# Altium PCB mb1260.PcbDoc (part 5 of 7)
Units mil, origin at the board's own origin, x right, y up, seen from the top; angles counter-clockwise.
Board outline 3189.01 x 3818.89 mil, 6 copper layers (TOP, L2_GND, L3_VCC, L4_SIG, L5_GND, BOTTOM), stack 62.2 mil thick; 308 components, 287 nets, 1220 pads, 851 vias.
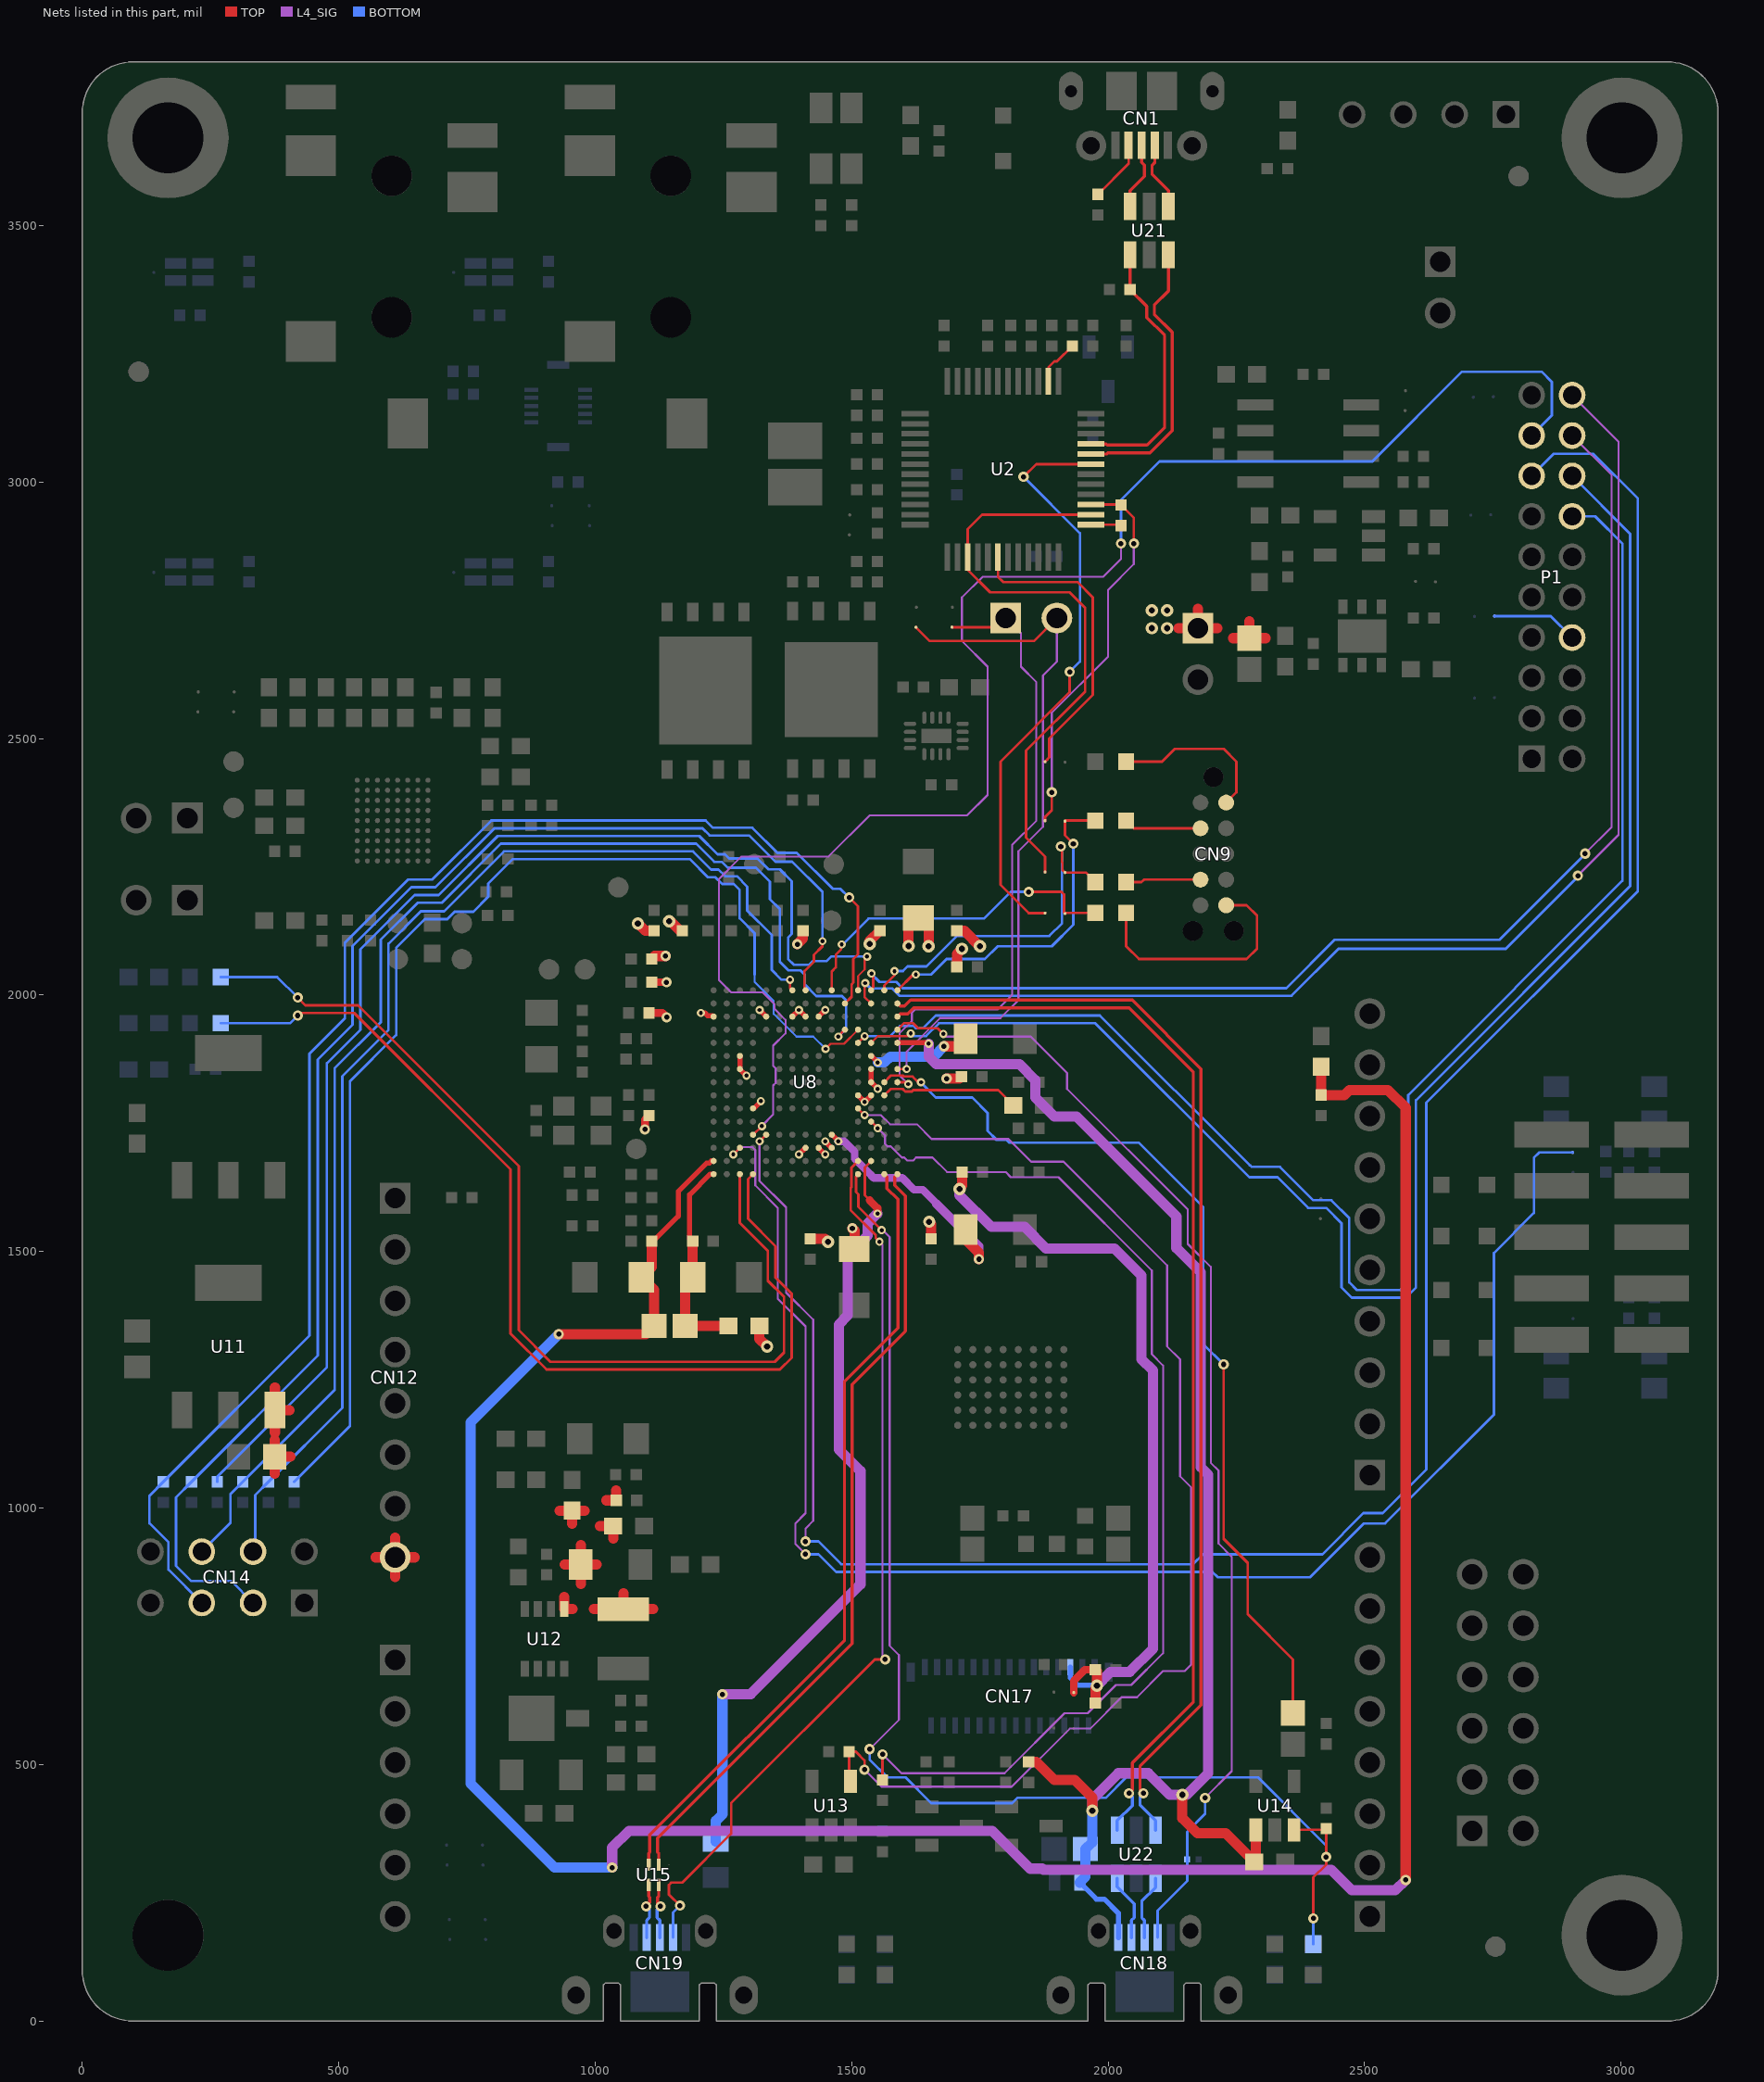
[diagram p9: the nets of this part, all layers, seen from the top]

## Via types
v1: diameter 24, hole 12, TOP to BOTTOM, tented both sides, 389 vias
v2: diameter 20, hole 10, TOP to BOTTOM, tented both sides, 231 vias
v3: diameter 16, hole 8, TOP to BOTTOM, tented both sides, 196 vias
v4: diameter 12, hole 6, TOP to BOTTOM, tented both sides, 35 vias

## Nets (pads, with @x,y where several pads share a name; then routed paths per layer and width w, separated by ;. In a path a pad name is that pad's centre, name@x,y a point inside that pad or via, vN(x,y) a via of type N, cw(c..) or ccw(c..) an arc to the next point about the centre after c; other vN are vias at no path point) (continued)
STMOD+_SPI2_MISOS: P1.9 U8.M4 | length 3145.4
  TOP w5: U8.M4@1307.64,1727.64 1308.14,1727.64 1325,1744.5 v3(1325.1,1744.5)
  L4_SIG w4: v3(1325.1,1744.5) 1325.1,1745.1 1347,1767 1347,1823.71 1352,1828.71 1352,1856.88 1347,1861.88 1347,1901.32 1371,1925.32 1371,1951.69 1349.68,1973.01 1349.68,1981.99 1326.68,2005 1265,2005 1241,2029 1241,2226 1285,2270 1455,2270 1535,2350 1725,2350 1765,2390 1765,2640 1715,2690 1715,2775 1755,2815 1990,2815 2025,2850 v2(2025,2880)
  BOTTOM w5: v2(2025,2880) 2025,2965 2100,3040 2515,3040 2690,3215 2845,3215 2865,3195 2865,3129.92 P1.9@2825.63,3090.55
STMOD+_SPI2_MOSIS: P1.8 U8.M5 | length 4476.8
  TOP w5: v3(1320.37,1714.91) 1320.5,1714.91 U8.M5@1333.23,1727.64
  L4_SIG w4: v3(1320.37,1714.91) 1320.37,1637.61 1372,1585.98 1372,1420 1425,1367 1425,975 1410,960 v2(1410,935)
  BOTTOM w5: v2(1410,935) 1435,935 1479.5,890.5 2165.5,890.5 2185,910 2417.56,910 2497.56,990 2535,990 2620,1075 2620,1790 3032.5,2202.5 3032.5,2967.5 2945,3055 2868.82,3055 P1.8@2825.63,3011.81
STMOD+_TIM2_CH1: P1.19 U8.A13 | length 2418.8
  TOP w5: U8.A13@1537.95,2009.13 1537.95,2010.08 1542.04,2014.17 1542.04,2037.96 1538.09,2041.91 v3(1538.52,2041.91)
  L4_SIG w4: P1.19@2904.37,3090.55 2981.57,3013.35 2981.57,2327.53 v2(2929.65,2275.61)
  BOTTOM w5: v3(1538.52,2041.91) 1537.63,2041.91 1554.06,2025.48 1586.81,2025.48 1598.79,2013.5 2347.51,2013.5 2441.68,2107.67 2762.67,2107.67 2929.65,2274.65 v2(2929.65,2275.61)
STMOD+_TIM3_CH3: P1.14 SB29.1 | length 168.7
  BOTTOM w5: SB29.1@2753.01,2738.67 2862.55,2738.67 P1.14@2904.37,2696.85
STMOD+_UART4_RXD: P1.18 U8.E13 | length 3186.7
  TOP w4: U8.E13@1537.95,1906.77 1550.86,1919.68 1609.68,1919.68 v3(1615,1925)
  BOTTOM w5: v3(1615,1925) 1620,1920 1645,1920 1670,1945 1975,1945 2275,1645 2330,1645 2390,1585 2425,1585 2455,1555 2455,1430 2475,1410 2580,1410 2600,1430 2600,1795 3017.5,2212.5 3017.5,2898.68 P1.18@2904.37,3011.81
STMOD+_UART4_RXD_S: P1.20 U8.B13 | length 2550.4
  TOP w5: v3(1526.47,2023.28) 1525,2021.81 1525,1996.49 U8.B13@1537.95,1983.54
  L4_SIG w4: P1.20@2904.37,3169.29 2995.03,3078.63 2995.03,2312.13 v2(2915.53,2232.63)
  BOTTOM w5: v3(1526.47,2023.28) 1536.92,2012.83 1578.63,2012.83 1592.96,1998.5 2357.5,1998.5 2449,2090 2775,2090 2915.53,2230.53 v2(2915.53,2232.63)
STMOD+_UART4_TXD: P1.17 U8.E12 | length 3132.5
  TOP w5: U8.E12@1512.36,1906.77 v3(1525.22,1919.63)
  BOTTOM w5: v3(1525.22,1919.63) 1574.63,1919.63 1594.5,1939.5 1621.01,1939.5 1625.51,1935 1638.78,1935 1663.78,1960 1983.78,1960 2275.78,1668 2277,1668 2280,1665 2335,1665 2400,1600 2435,1600 2470,1565 2470,1440 2485,1425 2570,1425 2585,1440 2585,1805 3002.5,2222.5 3002.5,2879.94 2949.37,2933.07 P1.17@2904.37,2933.07
SYS_B_USER: SB33.1 U8.N3 | length 3018.9
  TOP w5: v3(1269.19,1689.19) U8.N3@1282.05,1702.05
  L4_SIG w4: v3(1269.19,1689.19) 1283.32,1703.32 1306.5,1703.32 1312,1697.82 1312,1629 1356,1585 1356,1408 1410,1354 1410,990 1390,970 1390,930 v2(1410,910)
  BOTTOM w5: v2(1410,910) 1435,910 1469.5,875.5 2203.04,875.5 2213.54,865 2393.78,865 2498.78,970 2540,970 2752,1182 2752,1497 2830,1575 2830,1683.01 2840,1693.01 SB33.1@2905.33,1693.01
SYS_LD_USER1: R47.1 U8.R3 | length 1987
  TOP w5: v2(420,1995) 435,1980 537.63,1980 851,1666.63 851,1346.63 912.63,1285 1350,1285 1368,1303 1368,1411.56 1336.5,1443.06 1336.5,1501.5 1282.05,1555.95 U8.R3@1282.05,1650.87
  BOTTOM w5: R47.1@270,2035 380,2035 v2(420,1995)
SYS_LD_USER2: R48.1 U8.R4 | length 2003.2
  TOP w5: v2(420,1960) 425,1965 530,1965 835,1660 835,1340 905,1270 1360,1270 1383,1293 1383,1417.78 1351.5,1449.28 1351.5,1510.5 1298,1564 1298,1641.23 U8.R4@1307.64,1650.87
  BOTTOM w5: R48.1@270,1945 405,1945 v2(420,1960)
SYS_STLINK_JTCK: R38.2 SB12.2 U8.A14 | length 682.4
  TOP w5: U8.A14@1563.54,2009.13 1563.54,2018.54 1583.39,2038.39 v3(1583.39,2046.61) ; v2(1907.62,2289.45) 1910,2287.07 1910,2258.91 1910.69,2258.22 1910.69,2243.95 SB12.2@1915.83,2238.81 1956.19,2238.81 R38.2@1975,2220
  BOTTOM w5: v3(1583.39,2046.61) 1600,2046.61 1608.89,2055.5 1645.5,2055.5 1705,2115 1885,2115 1910,2140 1910,2287.07 v2(1907.62,2289.45)
SYS_STLINK_JTDO-SWO: R40.2 SB13.2 U8.A10 | length 673
  TOP w5: U8.A10@1461.18,2009.13 1461.18,2046.18 1469,2054 1469,2078.52 1479,2088.52 1479,2097.06 v3(1480.47,2098.53) ; v2(1845,2201) 1909,2201 1914,2196 1914,2160.64 SB13.2@1915.83,2158.81 1917.02,2160 R40.2@1975,2160
  BOTTOM w5: v3(1480.47,2098.53) 1482.53,2098.53 1533,2149 1758,2149 1810,2201 v2(1845,2201)
SYS_STLINK_JTMS: R32.2 SB11.2 U8.A15 | length 664
  TOP w5: U8.A15@1589.13,2009.13 1620,2040 v3(1625,2040) ; v2(1932,2295) 1915.83,2311.17 SB11.2@1915.83,2338.81 1917.02,2340 R32.2@1975,2340
  BOTTOM w5: v3(1625,2040) 1655,2040 1684.96,2069.96 1759.46,2069.96 1784.5,2095 1890,2095 1932,2137 v2(1932,2295)
T_JTCK: SB12.1 U2.15 U2.26 | length 1168.9
  TOP w5: SB12.1@1876.99,2239.67 1876.99,2270 1840,2306.99 1840,2476.22 1955,2591.22 1955,2755 1925,2785 1770,2785 1726.1,2828.9 U2.15@1726.1,2853.74 1726.1,2908.1 1754.42,2936.42 U2.26@1966.26,2936.42
T_JTMS: R23.1 SB11.1 U2.27 | length 756.5
  TOP w5: SB11.1@1876.99,2339.67 1876.99,2346.99 1890,2360 v2(1890,2395) ; U2.27@1966.26,2956.1 2023.9,2956.1 R23.1@2025,2955 2050,2930 v2(2050,2880)
  L4_SIG w4: v2(1890,2395) 1890,2550 2000,2660 2000,2790 2050,2840 v2(2050,2880)
T_NRST: SB10.1 U2.18 | length 599
  TOP w5: U2.18@1785.16,2853.74 1785.16,2815 1795.16,2805 1940,2805 1970,2775 1970,2585 1885,2500 1885,2463.07 1882.1,2460.17 1882.1,2459.78 SB10.1@1876.99,2454.67
T_SWDIO_IN: R23.2 U2.25 | length 59.5
  TOP w5: U2.25@1966.26,2916.73 2023.27,2916.73 R23.2@2025,2915
T_SWO: SB13.1 U2.31 | length 1156.4
  TOP w5: v2(1835,3010) 1859.84,3034.84 U2.31@1966.26,3034.84 ; SB13.1@1876.99,2159.67 1845,2159.67 1790,2214.67 1790,2455 1925,2590 v2(1925,2630)
  BOTTOM w5: v2(1835,3010) 1945,2900 1945,2650 v2(1925,2630)
TAG_NRST: CN9.10 R28.1 | length 323.8
  TOP w5: R28.1@2035,2455 2105,2455 2129.79,2479.79 2225.21,2479.79 2250,2455 2250,2395 CN9.10@2230,2375
TAG_SWCLK: CN9.4 R38.1 | length 147.1
  TOP w5: R38.1@2035,2220 2065,2220 2070,2225 CN9.4@2180,2225
TAG_SWDIO: CN9.2 R32.1 | length 151.2
  TOP w5: R32.1@2035,2340 2050,2325 CN9.2@2180,2325
TAG_SWO: CN9.6 R40.1 | length 471.9
  TOP w5: R40.1@2035,2160 2035,2095 2060,2070 2270,2070 2290,2090 2290,2155 2270,2175 CN9.6@2230,2175
USB_OTGFS_CN_N: CN18.2 U22.6 | length 130.8
  BOTTOM w6.1: U22.6@2017.6,277.76 2017.6,261.4 2050.57,228.43 2050.57,201.67 2045.28,196.38 CN18.2@2045.28,162.8
USB_OTGFS_CN_P: CN18.3 U22.4 | length 128.3
  BOTTOM w6.1: CN18.3@2070.87,162.8 2070.87,196.37 2065.57,201.67 2065.57,233.57 2092.4,260.4 U22.4@2092.4,277.76
USB_OTGFS_ID: CN18.4 U8.D15 U23.1 | length 2254.3
  TOP w5: U8.D15@1589.13,1932.36 1601.77,1945 1620,1945 1630,1935 1667.79,1935 v3(1678.63,1924.16)
  L4_SIG w4: v3(1678.63,1924.16) 1683.79,1919 1849,1919 1920,1848 1920,1817 2155,1582 2155,1515 2200,1470 2200,1088.29 2215,1073.29 2215,931 2241,905 2241,487 v2(2189,435)
  BOTTOM w5: CN18.4@2096.46,162.8 2096.46,215.44 2153.98,272.96 U23.1@2153.98,315 2153.98,368.98 2189,404 v2(2189,435)
USB_OTGFS_N: U8.C15 U22.1 | length 2180.2
  TOP w6.1: U8.C15@1589.13,1957.95 1594.42,1963.24 1609.46,1963.24 1621.22,1975 2040.78,1975 2166,1849.78 2166,622.22 2047.14,503.36 2047.14,450.36 v2(2040.64,443.86)
  BOTTOM w6.1: U22.1@2017.6,372.24 2017.6,390.6 2047.14,420.14 2047.14,437.36 v2(2040.64,443.86)
USB_OTGFS_OVCR: LD10.2 R79.1 U8.R12 U14.3 | length 2524.1
  TOP w5: U8.R12@1512.36,1650.87 1508.27,1646.78 1508.27,1615.95 1513,1611.22 1513,1587.29 v3(1558.47,1541.82) ; U14.3@2362.4,372.76 2422.76,372.76 R79.1@2425,375 v2(2425,320) 2425,305 2400,280 v2(2400,200)
  L4_SIG w4: v2(1535,530) 1592.11,587.11 1592.11,713.54 1574,731.65 1574,1528.44 1560.62,1541.82 v3(1558.47,1541.82)
  BOTTOM w5: v2(1535,530) 1535,510 1570,475 1605,475 1655,425 1813,425 1823,435 1995,435 2035,475 2292,475 2425,342 v2(2425,320) ; LD10.2@2400,150 v2(2400,200)
USB_OTGFS_P: U8.B15 U22.3 | length 2205.4
  TOP w6.1: U8.B15@1589.13,1983.54 1594.43,1978.24 1603.24,1978.24 1615,1990 2047,1990 2181,1856 2181,616 2062.14,497.14 2062.14,450.36 v2(2068.64,443.86)
  BOTTOM w6.1: v2(2068.64,443.86) 2062.14,437.36 2062.14,420.86 2092.4,390.6 U22.3@2092.4,372.24
USB_OTGFS_PPWR_EN: R72.1 U8.H14 | length 1812.9
  TOP w5: U8.H14@1563.54,1830 1576.54,1843 1599.21,1843 1601.12,1841.09 1618.91,1841.09 1630,1830 v3(1635,1830) ; v2(2225,1280) 2225,940 2272,893 2272,793 2360,705 R72.1@2360,600.51
  BOTTOM w5: v3(1635,1830) 1640,1825 1640,1824.02 1664.02,1800 1735,1800 1765,1770 1765,1735 1782.49,1717.5 1802.25,1717.5 1807.75,1712 2060,1712 2185,1587 2185,1320 v2(2225,1280)
USB_OTGFS_VBUS: C77.1 CN18.1 R77.2 R99.1 U8.E15 U14.1 U24.1 | length 2894.4
  TOP w10: U8.E15@1589.13,1906.77 1648.23,1906.77 v3(1650,1905)
  TOP w20: R77.2@1845,505 1860,505 1895,470 1935,470 1969,436 v1(1969,410) ; v1(2144.5,441) 2144.5,395.5 2174,366 2229,366 C77.1@2285,310 2287.6,312.6 U14.1@2287.6,372.76
  L4_SIG w20: v3(1650,1905) 1650,1880 1665,1865 1827,1865 1858,1834 1858,1800.41 1895.41,1763 1938,1763 2132.99,1568.01 2132.99,1507.01 2180,1460 2180,1080 2195,1065 2195,483 2153,441 v1(2144.5,441) 2120,441 2078,483 2020,483 1969,432 v1(1969,410)
  BOTTOM w10: U24.1@1944.61,270 1977.11,237.5 1992.5,237.5 2019.69,210.31 CN18.1@2019.69,162.8
  BOTTOM w20: U24.1@1944.61,270 1955.51,280.9 R99.1@1955.51,335 1969,348.49 v1(1969,410)
USB_OTGHS_CN_N: CN19.2 U15.2 | length 111.4
  TOP w6.1: v2(1099.18,223.76) 1106.5,231.08 1106.5,240.94 1104.16,243.28 U15.2@1104.16,265.31
  BOTTOM w6.1: v2(1099.18,223.76) 1105.68,217.26 1105.68,201.67 1100.39,196.38 CN19.2@1100.39,162.8
USB_OTGHS_CN_P: CN19.3 U15.3 | length 110.7
  TOP w6.1: U15.3@1123.84,265.31 1123.84,243.28 1121.5,240.94 1121.5,229.44 v2(1127.18,223.76)
  BOTTOM w6.1: CN19.3@1125.98,162.8 1125.98,196.37 1120.68,201.67 1120.68,217.26 v2(1127.18,223.76)
USB_OTGHS_ID: CN19.4 U8.P12 U15.4 | length 1760.9
  TOP w5: v2(1165,225) 1143.53,246.47 U15.4@1143.53,265.31 1148.22,270 1170,270 1265,365 1265,425 1545,705 v2(1565,705) ; U8.P12@1512.36,1676.46 1499.27,1663.37 1499.27,1625 1498,1623.73 1498,1580.4 1546.79,1531.61 1546.79,1526.21 v3(1554,1519)
  L4_SIG w4: v3(1554,1519) 1560,1513 1560,710 v2(1565,705)
  BOTTOM w5: CN19.4@1151.57,162.8 1151.57,211.57 v2(1165,225)
USB_OTGHS_N: U8.R14 U15.7 | length 1558.4
  TOP w6.1: U15.7@1104.16,304.69 1104.16,326.72 1106.5,329.06 1106.5,362.72 1486,742.22 1486,1247.22 1590,1351.22 1590,1601.78 1568.83,1622.95 1568.83,1645.58 U8.R14@1563.54,1650.87
USB_OTGHS_OVCR: R78.2 U8.L13 | length 2145.9
  TOP w5: U8.L13@1537.95,1753.23 v3(1550.81,1740.37) ; R78.2@1560,470 v2(1560,520)
  L4_SIG w4: v3(1550.81,1740.37) 1565,1726.18 1565,1710 1570,1705 1576.33,1705 1598.07,1683.26 1602.44,1683.26 1608.2,1677.5 1619.8,1677.5 1625.56,1683.26 1657.59,1683.26 1685.85,1655 1800,1655 1810,1645 1903.02,1645 2085,1463.02 2085,1300 2107,1278 2107,733.58 ; v2(1560,520) 1597,483 1798,483 1915,600 1960,600 2015,655 2045,655 2107.01,717.01 2107.01,733.57
USB_OTGHS_P: U8.R15 U15.6 | length 1558.4
  TOP w6.1: U15.6@1123.84,304.69 1123.84,326.72 1121.5,329.06 1121.5,356.5 1501,736 1501,1241 1605,1345 1605,1608 1583.83,1629.17 1583.83,1645.57 U8.R15@1589.13,1650.87
USB_OTGHS_PPWR_EN: R16.2 U8.K12 U13.4 | length 2389.8
  TOP w5: U13.4@1497.4,467.24 1495,469.64 R16.2@1495,525 1508,525 1525,508 v2(1525,490) ; U8.K12@1512.36,1778.82 v3(1525.22,1765.96)
  L4_SIG w4: v2(1525,490) 1558,457 1812,457 1925,570 1965,570 2026,631 2056,631 2107,682 2149,682 2162,695 2162,1040 2140,1062 2140,1290 2115,1315 2115,1473 1913,1675 1850,1675 1805.5,1719.5 1655.5,1719.5 1627,1748 1575,1748 1557.04,1765.96 v3(1525.22,1765.96)
USB_OTGHS_VBUS: R98.1 U8.P13 | length 1539.6
  TOP w5: 1535,1600 1525.45,1609.55 1525.45,1663.96 U8.P13@1537.95,1676.46
  TOP w15: 1535,1600 1550.32,1584.68 v3(1550.32,1574)
  L4_SIG w20: v2(1248,637) 1303,637 1517,851 1517,1072 1475,1114 1475,1358 1492.49,1375.49 1492.49,1492.49 1531,1531 1531,1554.68 v3(1550.32,1574)
  BOTTOM w20: R98.1@1235,350 1235,390 1248,403 v2(1248,637)
USB_RENUMN: R7.2 U2.38 | length 90.9
  TOP w5: U2.38@1883.58,3196.26 1883.58,3223.58 1895,3235 1900,3235 R7.2@1930,3265
USB_STLK_CN_N: CN1.2 U21.1 | length 134.6
  TOP w6.1: CN1.2@2090.94,3656.49 2090.94,3622.92 2085.64,3617.62 2085.64,3599.36 2117.4,3567.6 U21.1@2117.4,3537.24
USB_STLK_CN_P: CN1.3 U21.3 | length 133.1
  TOP w6.1: U21.3@2042.6,3537.24 2042.6,3567.6 2070.64,3595.64 2070.64,3617.62 2065.35,3622.91 CN1.3@2065.35,3656.49
USB_STLK_ID: CN1.4 R9.2 | length 120.7
  TOP w5: R9.2@1980,3560.59 2039.76,3620.35 CN1.4@2039.76,3656.49
USB_STLK_N: U2.32 U21.6 | length 546.2
  TOP w6.1: U2.32@1966.26,3054.53 1996.66,3054.53 1999,3056.87 2081.87,3056.87 2125,3100 2125,3292 2090,3327 2090,3345 2117.4,3372.4 U21.6@2117.4,3442.76
USB_STLK_P: R10.2 U2.33 U21.4 | length 523.4
  TOP w6.1: U2.33@1966.26,3074.21 1995.66,3074.21 1998,3071.87 2075.65,3071.87 2110,3106.22 2110,3285.78 2075,3320.78 2075,3342.6 R10.2@2042.6,3375 U21.4@2042.6,3442.76
V12_OTGPHY: C54.1 U8.J14 | length 272
  TOP w5: U8.J14@1563.54,1804.41 1576.04,1816.91 1599.25,1816.91 1604.25,1811.91 1617.42,1811.91 1620,1814.49 1785.51,1814.49 C54.1@1815,1785
VCAP1: C58.2 U8.M10 | length 479.2
  TOP w10: U8.M10@1461.18,1727.64 v3(1473.91,1714.91)
  TOP w20: C58.2@1722,1543 1722,1523.74 1748,1497.74 v2(1748,1485)
  L4_SIG w15: v3(1473.91,1714.91) 1485.09,1714.91 1505.72,1694.28 1505.72,1681.11 1531.24,1655.59 1531.24,1655.46 1543.2,1643.5 1598.5,1643.5 1621.5,1620.5 1638.58,1620.5 1665.47,1593.61 1665.47,1592.53
  L4_SIG w18: 1665.47,1592.53 1748,1510 v2(1748,1485)
VCAP2: C49.2 U8.F13 | length 208.6
  TOP w10: U8.F13@1537.95,1881.18 1538.08,1881.18 v3(1550.81,1868.45)
  TOP w20: v2(1680,1900) 1707,1900 C49.2@1722,1915
  BOTTOM w20: v3(1550.81,1868.45) 1563.45,1868.45 1575,1880 1660,1880 v2(1680,1900)
VCP_RX: CN6.2 SB8.1 U8.G15 | length 1392
  TOP w5: U8.G15@1589.13,1855.59 v3(1607.13,1855.59) ; SB8.1@1625.33,2716.99 1652.32,2690 1855,2690 CN6.2@1900,2735
  L4_SIG w4: v3(1607.13,1855.59) 1607.13,1889.59 1672.54,1955 1790,1955 1825,1990 1825,2280 1873,2328 1873,2623 1900,2650 CN6.2@1900,2735
VCP_TX: CN6.1 SB9.1 U8.H15 | length 1280.2
  TOP w5: U8.H15@1589.13,1830 1606.67,1830 v3(1610.26,1826.41) ; SB9.1@1695.33,2716.99 1781.99,2716.99 CN6.1@1800,2735
  L4_SIG w4: v3(1610.26,1826.41) 1593.13,1843.54 1593.13,1925 1617.46,1949.33 1617.46,1965.53 1623.93,1972 1785,1972 1813,2000 1813,2293 1860,2340 1860,2610 1830,2640 1830,2705 CN6.1@1800,2735
VDD: C34.1 C36.2 C37.2 C38.2 C39.2 C40.2 C44.2 C45.2 C46.2 C47.2 C52.2 C53.2 C56.2 C61.2 C62.2 C66.1 CN17.25 JP1.1 L1.1 R27.1 R68.1 R70.1 SB15.1 U8.C1 U8.C5 U8.C7 U8.C8 U8.C9 U8.F3 U8.G3 U8.G13 U8.H13 U8.J12 U8.J13 U8.K4 U8.N8 U8.N9 U8.N10 | length 2744
  TOP w10: v3(1206,1965) 1213.73,1965 1219.23,1959.5 1229.32,1959.5 U8.C1@1230.87,1957.95 ; U8.F3@1282.05,1881.18 U8.G3@1282.05,1855.59 v3(1294.91,1842.73) ; U8.K4@1307.64,1778.82 1308.69,1778.82 v3(1323,1793.13) ; v3(1320.37,1970.81) U8.C5@1333.23,1957.95 ; U8.C7@1384.41,1957.95 1384.28,1957.95 v3(1397.14,1970.81) U8.C8@1410,1957.95 ; v3(1397.27,1689.19) 1397.27,1689.68 1409.64,1702.05 U8.N8@1410,1702.05 ; U8.N9@1435.59,1702.05 1435.59,1701.96 v3(1448.36,1689.19) ; U8.C9@1435.59,1957.95 v3(1448.45,1970.81) ; v3(1448.38,1714.72) v3(1448.38,1714.72) 1461,1702.05 U8.N10@1461.18,1702.05 ; U8.J12@1512.36,1804.41 v3(1525.22,1791.55) 1537.95,1804.28 U8.J13@1537.95,1804.41 ; U8.G13@1537.95,1855.59 U8.H13@1537.95,1830 v3(1550.81,1817.14)
  TOP w15: v2(1097,1738) 1097,1757 C53.2@1105,1765 ; C47.2@1105,1965 1131,1965 1139.27,1956.73 v2(1139.35,1956.73) ; C46.2@1110,2025 v2(1139,2025) ; SB15.1@1933.01,640.33 1933.01,663.01 1955,685 R68.1@1975,685
  TOP w20: v1(1083.07,2139.35) 1097.42,2125 C36.2@1115,2125 ; C44.2@1110,2070 1116.12,2076.12 v2(1137,2076.12) ; v1(1144,2144) 1146,2144 1165,2125 C37.2@1170,2125 ; L1.1@1320,1355 1320,1330 v1(1335,1315) ; v2(1394,2099) 1405,2110 C38.2@1405,2125 ; C61.2@1419,1525 1448,1525 v1(1454,1519) ; v2(1501.27,1545.3) 1501.27,1544.73 1505.46,1540.54 1505.46,1505.46 C66.1@1505,1505 ; v1(1535,2099.57) 1535,2105 C39.2@1555,2125 ; v1(1610.9,2095.5) 1610.9,2130.9 C34.1@1630,2150 1650,2130 v1(1650,2095) ; v1(1651,1558) 1655,1554 C62.2@1655,1525 ; v2(1685,1837.16) C52.2@1710.16,1837.16 ; C45.2@1705,2055 1705,2080 v1(1715,2090) ; C40.2@1705,2125 1720,2125 v1(1750,2095) ; v1(1710.13,1622) 1710.13,1624.13 1715,1629 C56.2@1715,1655 ; R70.1@1975,620 1975,650.31 v1(1978.19,653.5) 1978.19,681.81 R68.1@1975,685 ; 2136.98,2715 JP1.1@2175,2715 ; 2175,2753.02 JP1.1@2175,2715 ; 2213.02,2715 JP1.1@2175,2715 ; 2243.48,2695.51 R27.1@2275,2695.51 ; 2275,2728.03 R27.1@2275,2695.51 ; 2306.52,2695.51 R27.1@2275,2695.51
  L4_SIG w20: v1(1710.13,1622) 1710.13,1609.87 1772,1548 1837,1548 1879,1506 2012,1506 2065,1453 2065,1290 2087,1268 2087,725.29 2041.71,680 2004.69,680 v1(1978.19,653.5)
  BOTTOM w10: CN17.25@1926.26,690.09 1926.26,668.74 1940,655 1976.69,655 v1(1978.19,653.5)
  other v1: 2085,2715 2115,2715 2085,2750 2115,2750
VDDA: C60.2 C65.1 L1.2 R62.2 U8.R1 | length 410.2
  TOP w10: C60.2@1190,1520 1184,1526 1184,1610.71 1224.16,1650.87 U8.R1@1230.87,1650.87
  TOP w20: C60.2@1190,1520 C65.1@1190,1450 1175.51,1425.51 R62.2@1175.51,1355 L1.2@1260,1355
VIN: C74.2 CN12.8 U11.3 | length 363.7
  TOP w20: 375,1066.98 C74.2@375,1100 ; 375,1133.02 C74.2@375,1100 ; 375.55,1147.46 U11.3@375.55,1190.98 ; 375.55,1234.5 U11.3@375.55,1190.98 ; 403.57,1190.98 U11.3@375.55,1190.98 ; 405.52,1100 C74.2@375,1100 ; 571.82,903.94 CN12.8@609.84,903.94 ; 609.84,865.92 CN12.8@609.84,903.94 ; 609.84,941.96 CN12.8@609.84,903.94 ; 647.86,903.94 CN12.8@609.84,903.94
VL: C70.2 C72.2 C73.2 L4.2 L6.1 U12.1 | length 485.8
  TOP w20: 930.98,995 L4.2@955,995 ; 939.39,826.59 U12.1@939.39,803.07 955.41,803.07 ; 940.98,890 C73.2@972,890 ; 955,969.48 L4.2@955,995 ; 972,851.98 C73.2@972,890 ; 972,928.02 C73.2@972,890 ; 979.02,995 L4.2@955,995 ; 996.98,803 L6.1@1055,803 ; 1003.02,890 C73.2@972,890 ; 1009.48,965 C72.2@1035,965 1035,940.98 ; 1021.98,1015 C70.2@1041,1015 1041,1034.02 ; 1055,834.02 L6.1@1055,803 ; 1113.02,803 L6.1@1055,803
VREF+: C50.2 C59.2 C64.1 R53.2 R62.1 U8.P1 | length 5280.1
  TOP w10: C59.2@1110,1520 1113,1520 1162,1569 1162,1617 1217.5,1672.5 1222.57,1672.5 1226.53,1676.46 U8.P1@1230.87,1676.46
  TOP w20: v2(928.96,1338.96) 1098.45,1338.96 R62.1@1114.49,1355 1114.49,1425.51 C64.1@1090,1450 1110,1470 C59.2@1110,1520 ; C50.2@2415,1860 R53.2@2415,1805 2460,1805 2470,1815 2545,1815 2580,1780 v2(2580,275)
  L4_SIG w20: v2(1033,299) 1033,338 1066,371 1774,371 1848.4,296.59 1848.81,297 1871.19,297 1873.19,295 2435,295 2475,255 2560,255 v2(2580,275)
  BOTTOM w20: v2(928.96,1338.96) 757.5,1167.5 757.5,462.5 921,299 v2(1033,299)
WIFI_CH_PD: CN14.6 R95.2 U8.D11 | length 2635.9
  TOP w5: v3(1473.87,1919) 1473.87,1920 1486.23,1932.36 U8.D11@1486.77,1932.36
  BOTTOM w5: CN14.6@232.99,915 289,971.01 289,1027 R95.2@313,1051 491.92,1229.92 491.92,1856.92 582,1947 582,2108.12 653.88,2180 676.22,2180 ; 676.23,2179.99 701.09,2179.99 816.1,2295 1196.66,2295 1232.16,2259.5 1246.74,2259.5 1258.24,2248 1313.56,2248 1340.5,2221.06 1340.5,2186.92 1360,2167.42 1360,2064.85 1376.83,2048.02 1399.98,2048.02 1408,2040 1408,2021 1431,1998 1481,1998 1489,1990 1489,1935 1473.87,1919.87 v3(1473.87,1919)
WIFI_GPIO_0: CN14.3 R93.2 U8.A8 | length 2800.5
  TOP w5: U8.A8@1410,2009.13 1408,2011.13 1408,2047 1426.1,2065.1 1426.1,2078.06 1443,2094.96 v3(1443,2105)
  BOTTOM w5: CN14.3@332.99,815 289.99,858 212,858 183,887 183,1021 R93.2@213,1051 459,1297 459,1874 527,1942 527,2095.56 641.44,2210 688.66,2210 803.66,2325 1209.1,2325 1223.1,2311 1300.2,2311 1351.2,2260 1384,2260 1443,2201 v3(1443,2105)
WIFI_GPIO_2: CN14.5 R96.2 U8.B11 | length 2854.6
  TOP w5: U8.B11@1486.77,1983.54 1499.86,1996.63 1499.86,2020.72 1503.13,2023.99 1503.13,2070.21 1512,2079.08 1512,2173 v2(1495,2190)
  BOTTOM w5: CN14.5@232.99,815 168,879.99 168,933 131,970 131,1024 R96.2@158,1051 443,1336 443,1885.44 512,1954.44 512,2101.78 635.22,2225 682.44,2225 797.44,2340 1215.32,2340 1229.32,2326 1306.42,2326 1355.42,2277 1393,2277 1463,2207 1478,2207 v2(1495,2190)
WIFI_RST: CN14.4 R94.2 U8.A7 | length 2345.2
  TOP w5: v3(1379.7,2029.86) 1379.7,2013.84 U8.A7@1384.41,2009.13
  BOTTOM w5: CN14.4@332.99,915 337,919.01 337,1025 R94.2@363,1051 506.92,1194.92 506.92,1841.92 597,1932 597,2100 660,2163 705.32,2163 822.32,2280 1190.44,2280 1225.94,2244.5 1240.52,2244.5 1253.52,2231.5 1276.3,2231.5 1296.5,2211.3 1296.5,2164.5 1344,2117 1344,2049 1363.14,2029.86 v3(1379.7,2029.86)
WIFI_RX: R92.1 U8.A12 | length 2516
  TOP w4: U8.A12@1512.36,2009.13 1512.36,2037 1525.18,2049.82
  TOP w5: 1525.18,2049.82 1525.18,2070.18 v3(1530,2075)
  BOTTOM w5: R92.1@263,1051 263,1061 476.92,1274.92 476.92,1866.92 542,1932 542,2089.34 647.66,2195 694.88,2195 809.88,2310 1202.88,2310 1238.38,2274.5 1252.96,2274.5 1261.14,2266.32 1316.46,2266.32 1337.78,2245 1360,2245 1383,2222 1383,2119 1376,2112 1376,2070.07 1387.07,2059 1417,2059 1424,2066 1451,2066 1460,2075 v3(1530,2075)
WIFI_TX: R97.2 U8.D12 | length 2382.1
  TOP w4: v3(1449,1895) 1459,1905 1485,1905 U8.D12@1512.36,1932.36
  BOTTOM w4: 1310.76,2040 1310.76,2025.24 1348,1988 1348,1963.24 1392.24,1919 1425.2,1919 1449,1895.2 v3(1449,1895)
  BOTTOM w5: R97.2@413,1051 521.92,1159.92 521.92,1831.92 612,1922 612,2092 668,2148 711.54,2148 726.04,2162.5 762.25,2162.5 791.37,2191.62 791.37,2217.37 839,2265 1184.22,2265 1219.72,2229.5 1234.3,2229.5 1247.3,2216.5 1270.08,2216.5 1281.5,2205.08 1281.5,2149.5 1310.76,2120.24 1310.76,2040
pads on no net: "CN4. " "CN5. " "CN9. " "CN17. " CN4.2 CN4.5 CN4.7 CN5.2 CN5.5 CN5.7 CN9.7 CN9.8 CN9.9 CN16.11 CN16.12 U2.4 U2.11 U2.14 U2.16 U2.17 U2.19 U2.21 U2.22 U2.29 U2.40 U2.41 U2.42 U2.43 U2.45 U2.46 U4.3 U4.5 U5.9 U6.9 U7.A6 U7.A8 U7.B4 U7.B5 U7.B8 U7.C4 U7.C5 U7.C7 U7.C8 U7.E1 U7.E5 U7.F4 U7.F5 U7.F6 U7.F8 U7.F9 U7.G4 U7.H2 U7.H3 U7.H4 U7.H5 U10.E3 U10.G2 U10.H6 U12.5 U20.17 U22.5
copper on no net: | length 1438.7
  TOP w8: 2276,1048 2336,1048 2336,1108 2276,1108 2276,1048.46 ; 2357,1048 2417,1048 2417,1108 2357,1108 2357,1048.17
  L4_SIG w8: 2275.99,1265.35 2335.99,1265.35 2335.99,1325.35 2275.99,1325.35 2275.99,1265.81 ; 2356.99,1265.35 2416.99,1265.35 2416.99,1325.35 2356.99,1325.35 2356.99,1265.52
  BOTTOM w8: 2276,1398 2276,1408 2276,1458 2336,1458 2336,1398 2276,1398 ; 2357,1398 2357,1408 2357,1458 2417,1458 2417,1398 2357,1398

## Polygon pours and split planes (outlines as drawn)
no net on TITLE_DATA (solid, pour order 155): 23 vertices, not listed, extent -300,-100 -200,0
no net on TITLE_DATA (solid, pour order 153): 23 vertices, not listed, extent -400,0 -300,100
no net on TITLE_DATA (solid, pour order 157): 170,3215 ccw(c110,3215) 110,3275 ccw(c110,3215) 50,3215 ccw(c110,3215) 110,3155 ccw(c110,3215) 170,3215
no net on TITLE_DATA (solid, pour order 161): 170,3215 ccw(c110,3215) 110,3275 ccw(c110,3215) 50,3215 ccw(c110,3215) 110,3155 ccw(c110,3215) 170,3215
no net on TITLE_DATA (solid, pour order 156): 2860,3596 ccw(c2800,3596) 2800,3656 ccw(c2800,3596) 2740,3596 ccw(c2800,3596) 2800,3536 ccw(c2800,3596) 2860,3596
no net on TITLE_DATA (solid, pour order 158): 2860,3596 ccw(c2800,3596) 2800,3656 ccw(c2800,3596) 2740,3596 ccw(c2800,3596) 2800,3536 ccw(c2800,3596) 2860,3596
no net on TITLE_DATA (solid, pour order 159): 2815,145 ccw(c2755,145) 2755,205 ccw(c2755,145) 2695,145 ccw(c2755,145) 2755,85 ccw(c2755,145) 2815,145
no net on TITLE_DATA (solid, pour order 160): 2815,145 ccw(c2755,145) 2755,205 ccw(c2755,145) 2695,145 ccw(c2755,145) 2755,85 ccw(c2755,145) 2815,145
no net on TITLE_DATA (solid, pour order 162): 31 vertices, not listed, extent 668.29,710 2078.29,3258.56
no net on TITLE_DATA (solid, pour order 152): 23 vertices, not listed, extent -300,-100 -200,0
no net on TITLE_DATA (solid, pour order 154): 23 vertices, not listed, extent -400,0 -300,100
E5V on TOP "E5V_L01_P116" (solid, pour order 116): 2798,1556 2934,1556 2938,1552 2938,1504 2936,1502 2770,1502 2764,1496 2709,1496 2704,1501 2704,1586 2709,1591 2764,1591 2774,1581 2774,1580 2798,1556
E5V on TOP "E5V_L01_P126" (solid, pour order 126): 77 vertices, not listed, extent 40,1265 365,1500
GND on TOP "GND_L01_P107" (solid, pour order 107): 41 vertices, not listed, extent 905,2317.52 957.48,2442.06
GND on TOP "GND_L01_P111" (solid, pour order 111): 305 vertices, not listed, extent 1433.04,2128.48 1575.88,2371.63
GND on TOP "GND_L01_P105" (solid, pour order 105): 70 vertices, not listed, extent 1394.02,2182.02 1418.05,2362.98
GND on TOP "GND_L01_P106" (solid, pour order 106): 39 vertices, not listed, extent 2633.12,2657.02 2668.98,2785.32
GND on TOP "GND_L01_P117" (solid, pour order 117): 56 vertices, not listed, extent 2603,2858.13 2720.98,3069.62
GND on TOP "GND_L01_P108" (solid, pour order 108): 2367.02,2685.02 2367.02,2723.52 2335.02,2723.52 2335.02,2740.01 2345,2750 2415,2750 2425,2740 2425,2685.02 2417.02,2685.02 2417.02,2702.02 2382.98,2702.02 2382.98,2685.02 2367.02,2685.02
GND on TOP "GND_L01_P109" (solid, pour order 109): 47 vertices, not listed, extent 2235,2765 2385,2822.98
VIN on TOP "VIN_L01_P127" (solid, pour order 127): 53 vertices, not listed, extent 350,835 710,1240
5V_USB_ST_LINK on TOP "5V_USB_ST_LINK_L01_P124" (solid, pour order 124): 17 vertices, not listed, extent 2691,1235 2936,1353
5V_USB_ST_LINK on TOP "5V_USB_ST_LINK_L01_P125" (solid, pour order 125): 89 vertices, not listed, extent 2190,3090 2625,3285
5V_USB_HS on TOP "5V_USB_HS_L01_P114" (solid, pour order 114): 20 vertices, not listed, extent 2703,1603 2939,1673
5V_ST_LINK on TOP "5V_ST_LINK_L01_P110" (solid, pour order 110): 57 vertices, not listed, extent 2540,3025 2635,3145
3V3_ST_LINK on TOP "3V3_ST_LINK_L01_P113" (solid, pour order 113): 20 vertices, not listed, extent 2235,2825 2460,2900
VDD on TOP "VDD_L01_P115" (solid, pour order 115): 19 vertices, not listed, extent 2055,2680 2315,2775
1V8 on TOP "1V8_L01_P128" (solid, pour order 128): 22 vertices, not listed, extent 60,1705 370,1980
5V on TOP "5V_L01_P129" (solid, pour order 129): 530 vertices, not listed, extent 2781.98,1270.99 3167.07,2899.89
5V on TOP "5V_L01_P112" (solid, pour order 112): 57 vertices, not listed, extent 2525,2600 2615,2790
3V3 on TOP "3V3_L01_P119" (solid, pour order 119): 340,1690 360,1710 450,1710 460,1700 460,1575 445,1560 355,1560 340,1575 340,1690
3V3 on TOP "3V3_L01_P120" (solid, pour order 120): 156 vertices, not listed, extent 2115,2545 2465,2665
5V_USB_FS on TOP "5V_USB_FS_L01_P118" (solid, pour order 118): 2701.99,1370.02 2697,1375 2697,1451 2704,1458 2931,1458 2938,1451 2938,1398 2937,1397 2769,1397 2742.01,1370.02 2701.99,1370.02
NETC75_2 on TOP "NETC75_2_L01_P121" (solid, pour order 121): 20 vertices, not listed, extent 790,360 910,660
GND on TOP "GND_L01_P123" (solid, pour order 123): 117 vertices, not listed, extent 825,1825 1181.13,2015
VL on TOP "VL_L01_P122" (solid, pour order 122): 99 vertices, not listed, extent 915,775 1140,1045
GND on TOP "GND_L01_P130" (solid, remove dead copper, pour order 130): 2467 vertices, not listed, extent 20.04,20.04 3168.97,3798.85
GND on L4_SIG "GND_L04_P145" (solid, pour order 145): 3786 vertices, not listed, extent 20.04,20.04 3168.97,3798.85
E5V on L4_SIG "E5V_L04_P131" (solid, pour order 131): 2670,1590 2675,1595 2760,1595 2765,1590 2765,1550 2760,1545 2680,1545 2670,1555 2670,1590
E5V on L4_SIG "E5V_L04_P134" (solid, pour order 134): 40,1431 50,1441 89,1441 95,1435 95,1341 90,1336 50,1336 40,1346 40,1431
GND on L4_SIG "GND_L04_P139" (solid, pour order 139): 252 vertices, not listed, extent 900,2765 2266,3388.98
GND on L4_SIG "GND_L04_P144" (solid, remove dead copper, pour order 144): 70 vertices, not listed, extent 20.04,555.02 551.33,1332
GND on L4_SIG "GND_L04_P143" (solid, pour order 143): 252 vertices, not listed, extent 2660,738 2986,1983
GND on L4_SIG "GND_L04_P141" (solid, pour order 141): 2092,2315 2133,2356 2376,2356 2402,2330 2402,1714 2366,1678 2168,1678 2092,1754 2092,2315
GND on L4_SIG "GND_L04_P142" (solid, pour order 142): 95 vertices, not listed, extent 1044,2574 1522,3154
GND on L4_SIG "GND_L04_P137" (solid, pour order 137): 20 vertices, not listed, extent 828,1827 1159.98,2014
5V_USB_HS on L4_SIG "5V_USB_HS_L04_P133" (solid, pour order 133): 31 vertices, not listed, extent 1027,230.5 1122,298
5V_USB_HS on L4_SIG "5V_USB_HS_L04_P136" (solid, pour order 136): 2725,1617 2714,1628 2714,1659 2727.99,1672.98 2829.01,1672.98 2855,1647 2855,1627 2845,1617 2725,1617
1V8 on L4_SIG "1V8_L04_P140" (solid, pour order 140): 460 vertices, not listed, extent 60,1625 705,2535
5V on L4_SIG "5V_L04_P138" (solid, pour order 138): 2620,2565 2559,2626 2559,2758 2576,2775 2685,2775 2810,2900 2930,2900 2960,2870 2960,2755 2940,2735 2800,2735 2775,2710 2775,2620 2720,2565 2620,2565
5V_USB_FS on L4_SIG "5V_USB_FS_L04_P135" (solid, pour order 135): 1863,428 1932,428 1941,419 1941,356 1930,345 1870,345 1855,360 1855,420 1863,428
5V_USB_FS on L4_SIG "5V_USB_FS_L04_P132" (solid, pour order 132): 2690.69,1328.79 2686,1333.48 2686,1393 2690.99,1397.98 2750.01,1397.98 2756,1392 2756,1333.48 2751.31,1328.79 2690.69,1328.79
GND on BOTTOM "GND_L06_P150" (solid, pour order 150): 98 vertices, not listed, extent 157.36,2452.36 485.48,2848.64
5V_USB_ST_LINK on BOTTOM "5V_USB_ST_LINK_L06_P148" (solid, pour order 148): 2538,3232 2548,3242 2618,3242 2625,3235 2625,3181 2615,3171 2553,3171 2538,3186 2538,3232
5V_USB_ST_LINK on BOTTOM "5V_USB_ST_LINK_L06_P149" (solid, pour order 149): 2660,1235 2650,1245 2650,1330 2655,1335 2715,1335 2720,1330 2720,1240 2715,1235 2660,1235
5V_USB_HS on BOTTOM "5V_USB_HS_L06_P146" (solid, pour order 146): 23 vertices, not listed, extent 1028,236 1119,289.5
5V_USB_FS on BOTTOM "5V_USB_FS_L06_P147" (solid, pour order 147): 1850,310 1845,315 1845,410 1857,422 1926,422 1934,414 1934,395 1924.5,385.5 1924.5,364.52 1863.98,364.52 1863.98,310 1850,310
GND on BOTTOM "GND_L06_P151" (solid, remove dead copper, pour order 151): 143 vertices, not listed, extent 0,0 3189.01,3818.89
GND on L2_GND (split plane): 270 vertices, not listed, extent 20.04,20.04 3168.98,3798.85
BLGND on L2_GND (split plane): 44 vertices, not listed, extent 790.09,360.09 1184.91,1169.91
no net on L3_VCC (split plane): 30 vertices, not listed, extent 1142.51,617.51 1152.71,627.72
5V on L3_VCC (split plane): 452 vertices, not listed, extent 500.09,429.69 3168.92,2899.91
3V3 on L3_VCC (split plane): 1412 vertices, not listed, extent 20.04,20.04 3168.98,3798.85
no net on L3_VCC (split plane): 1411.68,904.77 1411.22,904.64 1410.75,904.55 1410.27,904.51 1409.79,904.51 1409.32,904.55 1408.84,904.63 1408.38,904.75 1407.93,904.91 1407.92,904.91 1412.08,904.91
no net on L3_VCC (split plane): 26 vertices, not listed, extent 1493.88,2184.5 1500.5,2191.12
VDD on L3_VCC (split plane): 471 vertices, not listed, extent 1070.09,1295.09 2259.91,2819.91
3V3_ST_LINK on L3_VCC (split plane): 47 vertices, not listed, extent 1290.09,2840.09 3168.98,3798.85
no net on L3_VCC (split plane): 45 vertices, not listed, extent 1519.5,484.5 1530.5,491.46
no net on L3_VCC (split plane): 30 vertices, not listed, extent 2484.34,478.44 2512.06,505.64
no net on L3_VCC (split plane): 53 vertices, not listed, extent 2493.91,488.49 2535.31,529.42
no net on L3_VCC (split plane): 1570.24,706.69 1570.37,706.23 1570.45,705.76 1570.5,705.28 1570.5,704.8 1570.46,704.32 1570.38,703.85 1570.26,703.38 1570.1,702.93 1570.09,702.9 1570.09,707.1
no net on L3_VCC (split plane): 1535.23,2783.68 1535.36,2783.22 1535.45,2782.75 1535.49,2782.27 1535.49,2781.79 1535.45,2781.32 1535.37,2780.84 1535.25,2780.38 1535.09,2779.93 1535.09,2779.92 1535.09,2784.08
no net on L3_VCC (split plane): 35 vertices, not listed, extent 1744.8,1479.5 1753.5,1488.2
no net on L3_VCC (split plane): 24 vertices, not listed, extent 1788.86,1829.5 1797.51,1838.16
GND on L5_GND (split plane): 270 vertices, not listed, extent 20.04,20.04 3168.98,3798.85

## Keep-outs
Keep-Out Layer:
  pour cut-out: 2262.34,1532.61 2262.34,973.39 2426.92,973.39 2426.92,1532.61
  lines w1: 0,98.82 ccw(c98.82,98.82) 98.82,0 1015.74,0 1015.74,70.28 1019.68,74.22 1045.27,74.22 1049.21,70.28 1049.21,0 1202.75,0 1202.75,70.28 1206.69,74.22 1232.28,74.22 1236.22,70.28 1236.22,0 1960.63,0 1960.63,70.28 1964.57,74.22 1990.16,74.22 1994.1,70.28 1994.1,0 2147.64,0 2147.64,70.28 2151.58,74.22 2177.17,74.22 2181.11,70.28 2181.11,0 3090.19,0 ccw(c3090.19,98.82) 3189.01,98.82 3189.01,3720.07 ccw(c3090.19,3720.07) 3090.19,3818.89 98.82,3818.89 ccw(c98.82,3720.07) 0,3720.07 0,98.82
Drill Drawing:
  the board outline again, w1
Multi-Layer:
  lines w1: 251.99,167.33 ccw(c167.34,167.33) 251.99,167.33 ; 251.99,167.33 ccw(c167.34,167.33) 251.99,167.33 ; 305.34,167.33 ccw(c167.34,167.33) 305.34,167.33

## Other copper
TOP:
  drawing of 1996 lines, arcs and shapes, not listed
  text "D" at 2407,1092 h35 r90
  text "1" at 2324,1064 h35 r90
  text "1" at 2443.2,-1906.3 h75
  text "1" at 2443.2,-1906.3 h75
  text "PRIMARY SIDE" at 1943.2,-2056.3 h60
  text "PRIMARY SIDE" at 1943.2,-2056.3 h60
L4_SIG:
  drawing of 205 lines, arcs and shapes, not listed
  text "4" at 2323.36,1304.76 h35 r90
  text "D" at 2405,1283.79 h35 r90
BOTTOM:
  drawing of 973 lines, arcs and shapes, not listed
  text "6" at 2323,1438 h35 r90
  text "D" at 2404,1438 h35 r90
  text "6" at 2393.2,-1906.3 h75
  text "6" at 2393.2,-1906.3 h75
  text "SECONDARY SIDE" at 1943.2,-2056.3 h60
  text "SECONDARY SIDE" at 1943.2,-2056.3 h60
